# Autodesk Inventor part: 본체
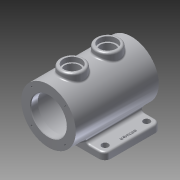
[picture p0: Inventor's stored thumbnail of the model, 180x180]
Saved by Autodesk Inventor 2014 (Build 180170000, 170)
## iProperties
Created: 2014-12
Part Number: 본체
Material: 알루미늄 6061
Document SubType Name: Modeling
Designer: Owner
Mass: 1293.94 g
Surface Area: 1039.34 cm^2
Volume: 477.47 cm^3
Density: 2.71 g/cm^3
Appearance: 알루미늄 - 평지
Author: Owner
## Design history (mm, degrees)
sketch "스케치1"
  geometry: C1 r 46 at (0, 0); 1 further point
  constraints: 1 centre point, 1 coincident
  dimensions: "d0" = 92 diameter of C1
extrude "돌출1" new body sketch "스케치1" stored distance "d1" = 140; taper "d2" = 0 deg
sketch "스케치2"
  geometry: C1 r 46 at (0, 0) reference; 1 further point
  constraints: 1 coincident
hole "구멍1" sketch "스케치2" at (0, 0) diameter "d3" = 60; stored, may be unused: countersink angle "d7" = 90 deg, drill point angle "d9" = 0 deg; dims "d4" = 6, "d5" = 4, "d6" = 2, "d8" = 12
sketch "스케치3"
  geometry: C1 r 30 at (0, 0) reference; 1 further point
  constraints: 1 coincident
hole "구멍2" sketch "스케치3" at (0, 0) diameter "d10" = 75; stored, may be unused: countersink angle "d14" = 90 deg, drill point angle "d16" = 0 deg; dims "d11" = 6, "d12" = 4, "d13" = 2, "d15" = 58
node "작업 평면1"
node "작업 평면2"
sketch "스케치11"
  geometry: L1 (-65, -40)-(65, -40); L2 (65, -40)-(65, 55); L3 (65, 55)-(-65, 55); L4 (-65, 55)-(-65, -40); 2 further points
  constraints: 8 end point, 2 parallel, 1 horizontal, 1 midpoint, 1 perpendicular, 1 vertical alignment
  dimensions: "d44" = 40 distance from line of L1 point (0, 0); "d45" = 55 distance from line of L3 point (0, 0); "d46" = 130 distance of L2.end L3.end
extrude "돌출4" join sketch "스케치11" distance "d47" = 12; taper "d48" = 0 deg
sketch "스케치12"
  geometry: L1 (25.923, -40)-(65, -40) reference; L2 (65, -40)-(65, 55) reference; 2 further points
  constraints: 1 other
  dimensions: "d49" = 47.5 distance from line of point (57, 7.5) L1; "d50" = 8 distance from line of L2 point (57, 7.5)
feature "엠보싱1" sketch "스케치12" dims "d2" = 0, "d44" = 40, "d45" = 55, "d46" = 130, "d51" = 1, "d52" = 0
sketch "스케치13"
  geometry: L1 (25.923, -40)-(65, -40) reference; L2 (65, -40)-(65, 55) reference; 2 further points
  dimensions: "d53" = 12.5 distance from line of point (52.5, -27) L2; "d54" = 13 distance from line of point (52.5, -27) L1
hole "구멍5" sketch "스케치13" at (52.5, -27) diameter "d55" = 11; stored, may be unused: countersink angle "d59" = 90 deg, drill point angle "d61" = 0 deg; dims "d56" = 6, "d57" = 4, "d58" = 2, "d60" = 50
sketch "스케치14"
  geometry: L1 (0, 0)-(28.284, 28.284); L2 (0, 0)-(40, 0); C1 r 46 at (0, 0) reference; 1 further point
  constraints: 4 end point, 1 coincident, 1 equal length, 1 horizontal
  dimensions: "d68" = 40 distance of L1.start L1.end; "d69" = 45 deg angle of L2 L1
hole "구멍6" sketch "스케치14" at (28.284, 28.284) diameter "d70" = 3.242; stored, may be unused: countersink angle "d74" = 90 deg, drill point angle "d76" = 118 deg; dims "d71" = 8, "d72" = 4, "d73" = 2, "d75" = 10
fillet "모깎기2" dims "d81" = 5
fillet "모깎기5" dims "d84" = 3
fillet "모깎기6" dims "d85" = 10
fillet "모깎기7" dims "d86" = 3
chamfer "모따기1" distance "d87" = 1; stored, may be unused: second distance "d88" = 2, angle "d89" = 45 deg
fillet "모깎기8" dims "d90" = 3
node "작업 평면4"
  node "작업 평면3"
sketch "스케치16"
  geometry: L1 (-35.072, 58)-(-35.072, -43) reference; L2 (35.072, -43)-(-35.072, -43) reference; L3 (35.072, -43)-(35.072, 58) reference; L4 (-35.072, 58)-(35.072, 58) reference; L5 (-46, -70)-(46, -70) reference; L6 (46, 70)-(-46, 70) reference; C1 r 20 at (0, 30); C2 r 20 at (0, -30); 1 further point
  constraints: 2 centre point, 2 vertical alignment, 1 equal radius
  dimensions: "d93" = 40 distance from line of C1.centre L6; "d94" = 60 distance of C2.centre C1.centre; "d95" = 40 diameter of C1
extrude "돌출5" join sketch "스케치16" stored distance "d96" = 10; taper "d97" = 0 deg
sketch "스케치17"
  geometry: C1 r 20 at (0, 0) reference; C2 r 15 at (0, 0); 1 further point
  constraints: 1 centre point, 1 coincident
  dimensions: "d98" = 30 diameter of C2
extrude "돌출6" cut sketch "스케치17" distance "d99" = 8; taper "d100" = 0 deg
sketch "스케치18"
  geometry: C1 r 15 at (0, 0) reference; C2 r 12.5 at (0, 0); 1 further point
  constraints: 1 centre point, 1 coincident
  dimensions: "d101" = 25 diameter of C2
extrude "돌출7" cut sketch "스케치18" stored distance "d102" = 8; taper "d103" = 0 deg
fillet "모깎기9" dims "d104" = 3
node "솔리드1"
mirror "대칭1"
pattern_linear "직사각형 패턴1" dims "d64" = 70, "d67" = 104
pattern_circular "원형 패턴1" dims angle "d78" = 360 deg
mirror "대칭3"
mirror "대칭4"
node "투영된 루프1"
other parameters: "d17" = 54, "d92" = 106
